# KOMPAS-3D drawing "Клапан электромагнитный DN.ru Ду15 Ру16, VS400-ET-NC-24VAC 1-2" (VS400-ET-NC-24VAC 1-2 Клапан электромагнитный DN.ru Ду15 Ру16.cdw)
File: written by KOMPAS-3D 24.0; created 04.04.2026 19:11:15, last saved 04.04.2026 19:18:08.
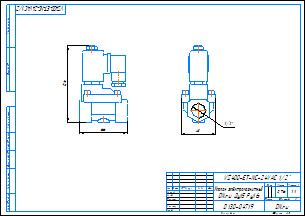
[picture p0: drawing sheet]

Document properties: c3d_UniqueCompID: ef56311e-7521-43dc-8291-0e6108b3d81d; Обозначение: VS400-ET-NC-220VAC 1-2; Наименование: Клапан электромагнитный DN.ru Ду15 Ру16; Автор: artio; Класс точности: c; Знак неуказанной шероховатости: Шероховатость не задана; Рассекать на разрезах: Да; c3d_UniqueCompID: ef56311e-7521-43dc-8291-0e6108b3d81d; Обозначение: VS400-ET-NC-220VAC 3-8; Наименование: Клапан электромагнитный DN.ru Ду10 Ру16; Автор: artio; Класс точности: c; Знак неуказанной шероховатости: Шероховатость не задана; Рассекать на разрезах: Да; Автор: artio; Форматы листов документа: A3; Полное имя файла: VS400-ET-NC-24VAC 1-2 Клапан электромагнитный DN.ru Ду15 Ру16.m3d; Масса: 0.759; Наименование: Клапан электромагнитный DN.ru Ду15 Ру16; Количество листов документа: 1; Примечание: D130-05629

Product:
- Body: Тело 1  | qty 1
    Масса: 1.030062
- Part/product: Клапан электромагнитный DN.ru Ду15 Ру16  | designation VS400-ET-NC-24VAC 1-2
    Масса: 0.759
    Раздел спецификации: Прочие изделия
    Примечание: D130-05629
    additional columns: ef56311e-7521-43dc-8291-0e6108b3d81d; VS400-ET-NC-220VAC 1-2; artio; c; Шероховатость не задана; Да

Views: Вид 1, Спереди, Проекционный вид 2
Referenced files in C:\Users\artio\OneDrive\Рабочий стол\Клапан электромагнитный DN.ru\VS400-ET-NC\VS400-ET-NC-24VDC\: VS400-ET-NC-24VDC 3-8 Клапан электромагнитный DN.ru Ду10 Ру16.m3d
Referenced files in C:\Users\artio\OneDrive\Рабочий стол\Клапан электромагнитный DN.ru\VS400-ET-NC\VS400-ET-NC-24VAC\: VS400-ET-NC-24VAC 1-2 Клапан электромагнитный DN.ru Ду15 Ру16.m3d
Referenced files in C:\Users\artio\OneDrive\Рабочий стол\Клапан электромагнитный DN.ru\VS400-ET-NC\: VS400-ET-NC-24VDC 3-8 Клапан электромагнитный DN.ru Ду10 Ру16.cdw
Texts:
  VS400-ET-NC-24VAC 1-2
  Клапан электромагнитный
  DN.ru Ду15 Ру16
  VS400-ET-NC-24VAC 1/2"
  VS400-ET-NC-24VAC 1/2"-
  Клапан электромагнитный DN.ru Ду15 Ру16
  VS400-ET-NC-24VAC 1-2 Клапан электромагнитный DN.ru Ду15 Ру16
Dimensions and other numbers on the sheet: 0; 3; 2; 4; 48; 1/2"; 66; 106; 1:1; 1; 0,76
